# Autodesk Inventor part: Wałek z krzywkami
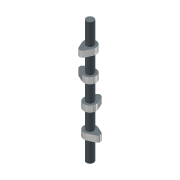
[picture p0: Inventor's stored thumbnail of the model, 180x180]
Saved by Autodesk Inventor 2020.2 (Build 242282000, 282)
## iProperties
Created: 2005-10
Part Number: Wałek z krzywkami
Document SubType Name: Modeling
Designer: F.Stasiak
Density: 1 g/cm^3
Material: Ogólny
Appearance: Niebieski szary (jasny)
Manager: www.cadconsulting.pl
Company: Fabian Stasiak CAD Consulting
Author: F.Stasiak
Subject: Zbiór ćwiczeń. Autodesk Inventor 2020. Kurs podstawowy
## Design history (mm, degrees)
sketch "Szkic1"
  geometry: C1 r 3 at (0, 0)
  constraints: 1 centre point
  dimensions: "d0" = 6 diameter of C1
extrude "Wyciągnięcie proste1" new body sketch "Szkic1" distance "d1" = 100; taper "d2" = 0 deg
node "Płaszczyzna konstrukcyjna1"
sketch "Szkic2"
  geometry: L1 (-6, 0)-(0, 0); L2 (-2.083, -4.545)-(-7.042, -2.273); L3 (-2.083, 4.545)-(-7.042, 2.273); C1 r 3 at (0, 0) reference; A1 r 5 centre (0, 0) between (-2.083, -4.545) and (-2.083, 4.545); A2 r 2.5 centre (-6, 0) between (-7.042, 2.273) and (-7.042, -2.273)
  constraints: 6 end point, 4 point on circle, 4 tangent, 2 centre point, 1 coincident, 1 horizontal
  dimensions: "d4" = 10 diameter of A1; "d5" = 5 diameter of A2; "d6" = 6 distance of L1.start L1.end
extrude "Wyciągnięcie proste2" join sketch "Szkic2" stored distance "d7" = 5; taper "d8" = 0 deg
node "Płaszczyzna konstrukcyjna2"
sketch "Szkic3"
  geometry: L1 (2.273, 7.042)-(4.545, 2.083); L2 (-4.545, 2.083)-(-2.273, 7.042); L3 (0, 6)-(0, 0.391); L4 (0, -6.681)-(0, 12.794) reference; C1 r 3 at (0, 0) reference; A1 r 5 centre (0, 0) between (-4.545, 2.083) and (4.545, 2.083); A2 r 2.5 centre (0, 6) between (2.273, 7.042) and (-2.273, 7.042)
  constraints: 6 end point, 4 point on circle, 4 tangent, 2 centre point, 1 collinear, 1 concentric, 1 point on line
  dimensions: "d10" = 5 radius of A1; "d11" = 2.5 radius of A2; "d12" = 6 distance of A1.centre L3.start
extrude "Wyciągnięcie proste3" join sketch "Szkic3" stored distance "d13" = 5; taper "d14" = 0 deg
node "Płaszczyzna konstrukcyjna3"
sketch "Szkic4"
  geometry: L1 (7.042, -2.273)-(2.083, -4.545); L2 (2.083, 4.545)-(7.042, 2.273); L3 (10.343, 0)-(-13.639, 0) reference; L4 (0, 0)-(6, 0); C1 r 3 at (0, 0) reference; A1 r 5 centre (0, 0) between (2.083, 4.545) and (2.083, -4.545); A2 r 2.5 centre (6, 0) between (7.042, -2.273) and (7.042, 2.273)
  constraints: 6 end point, 4 point on circle, 4 tangent, 2 centre point, 1 collinear, 1 concentric
  dimensions: "d16" = 5 radius of A1; "d17" = 2.5 radius of A2; "d18" = 6 distance of A1.centre L4.end
extrude "Wyciągnięcie proste4" join sketch "Szkic4" stored distance "d19" = 5; taper "d20" = 0 deg
node "Płaszczyzna konstrukcyjna4"
sketch "Szkic5"
  geometry: L1 (-2.273, -7.042)-(-4.545, -2.083); L2 (4.545, -2.083)-(2.273, -7.042); L3 (0, 0)-(0, -6); L4 (0, -6.708)-(0, 12.648) reference; C1 r 3 at (0, 0) reference; A1 r 2.5 centre (0, -6) between (-2.273, -7.042) and (2.273, -7.042); A2 r 5 centre (0, 0) between (4.545, -2.083) and (-4.545, -2.083)
  constraints: 6 end point, 4 point on circle, 4 tangent, 2 centre point, 1 collinear, 1 concentric
  dimensions: "d22" = 2.5 radius of A1; "d23" = 5 radius of A2; "d24" = 6 distance of L3.end C1.centre
extrude "Wyciągnięcie proste5" join sketch "Szkic5" stored distance "d25" = 5; taper "d26" = 0 deg
node "Bryła1"
node "Korpusy bryłowe"
node "Korpusy powierzchniowe"
node "Pętla rzutowana2"
